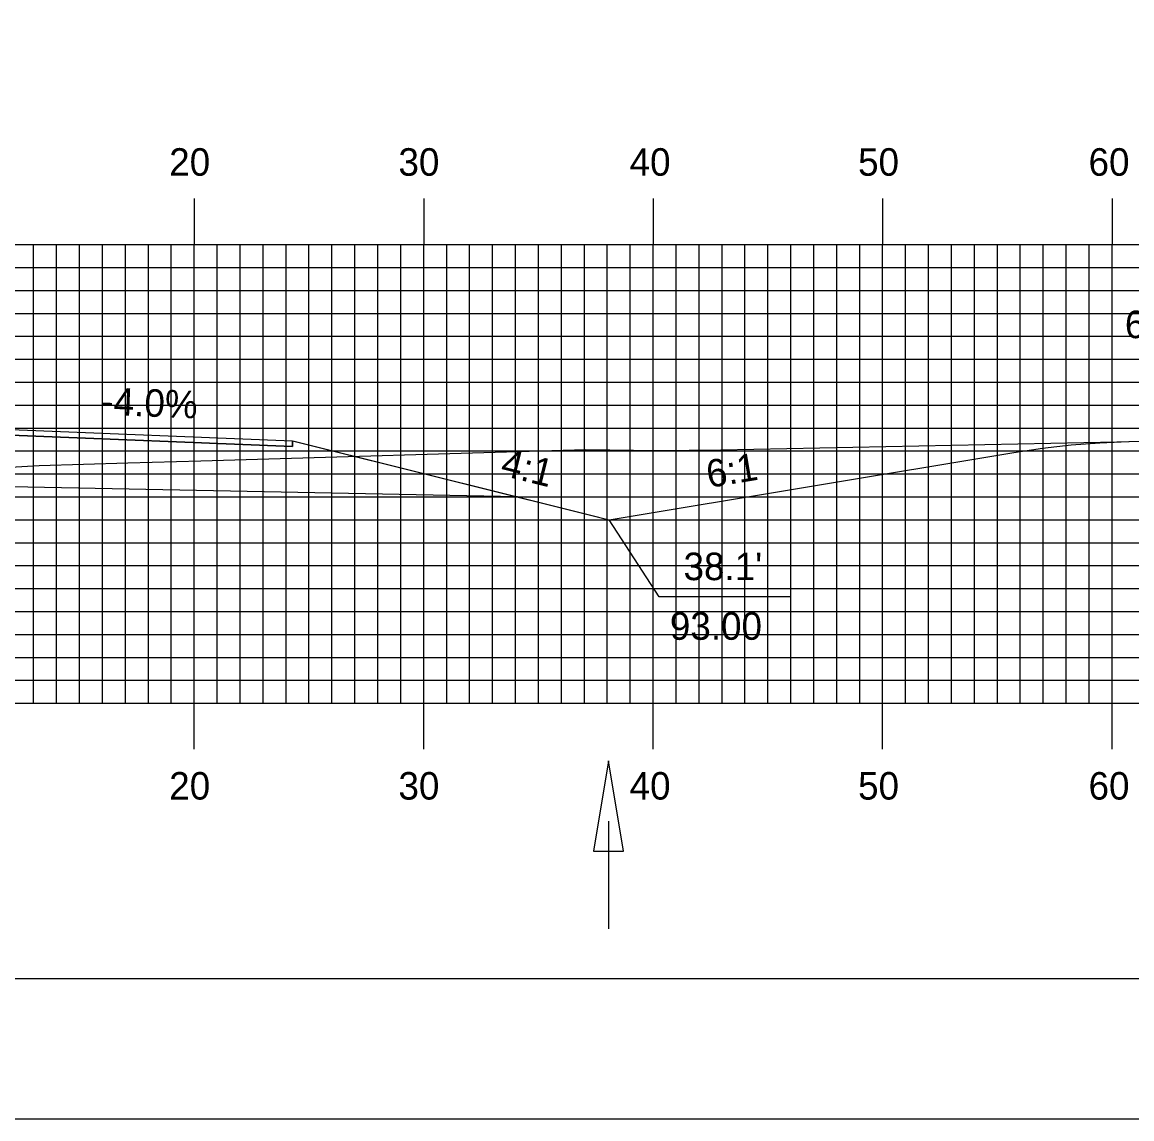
# Model space of a CAD drawing. Extents: x 1775564 to 1775907, y 442591 to 442811.
# Drawn here: x 1775742.21 to 1775790.57, y 442590.55 to 442638.36 of the extents above; entities that cross this region are included whole.
import ezdxf

# ---------------------------------------------------------------- set-up
doc = ezdxf.new("R2010")
doc.units = 0
for name, color, linetype in [('ANNOTATION', 7, 'Continuous'), ('BORDER', 7, 'Continuous'), ('D_Drainage_Ditch_Line', 7, 'Continuous'), ('D_Roadway_Centerline', 7, 'Continuous'), ('D_Roadway_Edge_Shoulder', 7, 'Continuous'), ('D_Roadway_SlopeLines', 7, 'Continuous'), ('D_Roadway_SubGrade', 7, 'Continuous'), ('D_Text_Standard', 7, 'Continuous'), ('H_V ANNOTATION', 7, 'Continuous'), ('MAJOR', 7, 'Continuous'), ('MINOR', 7, 'Continuous'), ('PLOT BOUNDARY', 7, 'Continuous'), ('S_Roadway_Centerline', 7, 'Continuous')]:
    doc.layers.add(name, color=color, linetype=linetype)

msp = doc.modelspace()

# ---------------------------------------------------------------- linework, layer by layer
at = {"layer": 'ANNOTATION'}
msp.add_lwpolyline([(1775775.668, 442613.306), (1775769.977, 442613.306), (1775767.799, 442616.662)], dxfattribs=at)
at = {"layer": 'BORDER'}
msp.add_lwpolyline([(1775580.111, 442596.665), (1775900.111, 442596.665), (1775900.111, 442806.665), (1775580.111, 442806.665)], close=True, dxfattribs=at)
at = {"layer": 'D_Drainage_Ditch_Line'}
msp.add_line((1775767.763, 442603.524), (1775767.763, 442598.825), dxfattribs=at)
msp.add_lwpolyline([(1775767.107, 442602.211), (1775768.419, 442602.211), (1775767.763, 442606.148)], close=True, dxfattribs=at)
at = {"layer": 'D_Roadway_Centerline'}
msp.add_lwpolyline([(1775741.711, 442620.604), (1775753.997, 442620.112), (1775754.058, 442620.097), (1775763.799, 442617.662), (1775766.937, 442616.878), (1775767.799, 442616.662), (1775785.431, 442619.6), (1775786.68, 442619.786), (1775787.929, 442619.927), (1775787.929, 442619.927), (1775789.181, 442620.022), (1775790.429, 442620.072)], dxfattribs=at)
at = {"layer": 'D_Roadway_Edge_Shoulder'}
msp.add_lwpolyline([(1775741.711, 442620.604), (1775753.997, 442620.112), (1775753.997, 442619.862), (1775741.711, 442620.354)], close=True, dxfattribs=at)
at = {"layer": 'D_Roadway_SlopeLines'}
for points in [[(1775753.997, 442620.112), (1775767.799, 442616.662)], [(1775767.799, 442616.662), (1775785.43, 442619.6), (1775786.68, 442619.786), (1775787.929, 442619.927), (1775789.18, 442620.022), (1775790.429, 442620.072)]]:
    msp.add_lwpolyline(points, dxfattribs=at)
at = {"layer": 'D_Roadway_SubGrade'}
msp.add_lwpolyline([(1775717.712, 442618.104), (1775699.537, 442617.74), (1775709.711, 442620.284), (1775709.711, 442620.034), (1775717.712, 442620.354), (1775729.712, 442620.594), (1775741.711, 442620.354), (1775753.997, 442619.862), (1775753.997, 442620.112), (1775763.798, 442617.662), (1775741.711, 442618.104), (1775729.712, 442618.344)], close=True, dxfattribs=at)
at = {"layer": 'MAJOR'}
for p, q in [((1775749.711, 442630.669), (1775749.711, 442628.665)), ((1775759.711, 442630.669), (1775759.711, 442628.665)), ((1775769.711, 442630.669), (1775769.711, 442628.665)), ((1775779.711, 442630.669), (1775779.711, 442628.665)), ((1775789.711, 442630.669), (1775789.711, 442628.665)), ((1775589.711, 442628.665), (1775869.711, 442628.665)), ((1775589.711, 442628.665), (1775869.711, 442628.665)), ((1775749.711, 442608.665), (1775749.711, 442628.665)), ((1775759.711, 442608.665), (1775759.711, 442628.665)), ((1775769.711, 442608.665), (1775769.711, 442628.665)), ((1775779.711, 442608.665), (1775779.711, 442628.665)), ((1775789.711, 442608.665), (1775789.711, 442628.665)), ((1775589.711, 442623.665), (1775869.711, 442623.665)), ((1775589.711, 442618.665), (1775869.711, 442618.665)), ((1775589.711, 442613.665), (1775869.711, 442613.665)), ((1775589.711, 442608.665), (1775869.711, 442608.665)), ((1775589.711, 442608.665), (1775869.711, 442608.665)), ((1775749.711, 442606.661), (1775749.711, 442608.665)), ((1775759.711, 442606.661), (1775759.711, 442608.665)), ((1775769.711, 442606.661), (1775769.711, 442608.665)), ((1775779.711, 442606.661), (1775779.711, 442608.665)), ((1775789.711, 442606.661), (1775789.711, 442608.665))]:
    msp.add_line(p, q, dxfattribs=at)
at = {"layer": 'MINOR'}
for p, q in [((1775742.711, 442608.665), (1775742.711, 442628.665)), ((1775743.711, 442608.665), (1775743.711, 442628.665)), ((1775744.711, 442608.665), (1775744.711, 442628.665)), ((1775745.711, 442608.665), (1775745.711, 442628.665)), ((1775746.711, 442608.665), (1775746.711, 442628.665)), ((1775747.711, 442608.665), (1775747.711, 442628.665)), ((1775748.711, 442608.665), (1775748.711, 442628.665)), ((1775750.711, 442608.665), (1775750.711, 442628.665)), ((1775751.711, 442608.665), (1775751.711, 442628.665)), ((1775752.711, 442608.665), (1775752.711, 442628.665)), ((1775753.711, 442608.665), (1775753.711, 442628.665)), ((1775754.711, 442608.665), (1775754.711, 442628.665)), ((1775755.711, 442608.665), (1775755.711, 442628.665)), ((1775756.711, 442608.665), (1775756.711, 442628.665)), ((1775757.711, 442608.665), (1775757.711, 442628.665)), ((1775758.711, 442608.665), (1775758.711, 442628.665)), ((1775760.711, 442608.665), (1775760.711, 442628.665)), ((1775761.711, 442608.665), (1775761.711, 442628.665)), ((1775762.711, 442608.665), (1775762.711, 442628.665)), ((1775763.711, 442608.665), (1775763.711, 442628.665)), ((1775764.711, 442608.665), (1775764.711, 442628.665)), ((1775765.711, 442608.665), (1775765.711, 442628.665)), ((1775766.711, 442608.665), (1775766.711, 442628.665)), ((1775767.711, 442608.665), (1775767.711, 442628.665)), ((1775768.711, 442608.665), (1775768.711, 442628.665)), ((1775770.711, 442608.665), (1775770.711, 442628.665)), ((1775771.711, 442608.665), (1775771.711, 442628.665)), ((1775772.711, 442608.665), (1775772.711, 442628.665)), ((1775773.711, 442608.665), (1775773.711, 442628.665)), ((1775774.711, 442608.665), (1775774.711, 442628.665)), ((1775775.711, 442608.665), (1775775.711, 442628.665)), ((1775776.711, 442608.665), (1775776.711, 442628.665)), ((1775777.711, 442608.665), (1775777.711, 442628.665)), ((1775778.711, 442608.665), (1775778.711, 442628.665)), ((1775780.711, 442608.665), (1775780.711, 442628.665)), ((1775781.711, 442608.665), (1775781.711, 442628.665)), ((1775782.711, 442608.665), (1775782.711, 442628.665)), ((1775783.711, 442608.665), (1775783.711, 442628.665)), ((1775784.711, 442608.665), (1775784.711, 442628.665)), ((1775785.711, 442608.665), (1775785.711, 442628.665)), ((1775786.711, 442608.665), (1775786.711, 442628.665)), ((1775787.711, 442608.665), (1775787.711, 442628.665)), ((1775788.711, 442608.665), (1775788.711, 442628.665)), ((1775589.711, 442627.665), (1775869.711, 442627.665)), ((1775589.711, 442626.665), (1775869.711, 442626.665)), ((1775589.711, 442625.665), (1775869.711, 442625.665)), ((1775589.711, 442624.665), (1775869.711, 442624.665)), ((1775589.711, 442622.665), (1775869.711, 442622.665)), ((1775589.711, 442621.665), (1775869.711, 442621.665)), ((1775589.711, 442620.665), (1775869.711, 442620.665)), ((1775589.711, 442619.665), (1775869.711, 442619.665)), ((1775589.711, 442617.665), (1775869.711, 442617.665)), ((1775589.711, 442616.665), (1775869.711, 442616.665)), ((1775589.711, 442615.665), (1775869.711, 442615.665)), ((1775589.711, 442614.665), (1775869.711, 442614.665)), ((1775589.711, 442612.665), (1775869.711, 442612.665)), ((1775589.711, 442611.665), (1775869.711, 442611.665)), ((1775589.711, 442610.665), (1775869.711, 442610.665)), ((1775589.711, 442609.665), (1775869.711, 442609.665))]:
    msp.add_line(p, q, dxfattribs=at)
at = {"layer": 'PLOT BOUNDARY'}
msp.add_lwpolyline([(1775563.925, 442590.547), (1775903.925, 442590.547), (1775903.925, 442810.547), (1775563.925, 442810.547)], close=True, dxfattribs=at)
at = {"layer": 'S_Roadway_Centerline'}
msp.add_lwpolyline([(1775671.367, 442617.314), (1775677.368, 442617.226), (1775681.932, 442617.369), (1775694.75, 442617.701), (1775704.446, 442617.76), (1775718.287, 442617.975), (1775727.836, 442618.408), (1775734.374, 442618.543), (1775742.951, 442619.027), (1775746.809, 442619.145), (1775750.001, 442619.229), (1775766.783, 442619.727), (1775769.905, 442619.679), (1775772.654, 442619.714), (1775789.917, 442620.057), (1775792.569, 442620.138)], dxfattribs=at)

# ---------------------------------------------------------------- texts
at = {"layer": 'ANNOTATION'}
for s, rotation, p in [('-4.0%', 357.7069, (1775745.646, 442621.248)), ('4:1', 345.9653, (1775763.006, 442618.619)), ('6:1', 9.4604, (1775772.135, 442618.051))]:
    msp.add_text(s, height=1.2, rotation=rotation, dxfattribs=at).set_placement(p)
for s, p in [("38.1'", (1775771.033, 442614.032)), ('93.00', (1775770.438, 442611.432))]:
    msp.add_text(s, height=1.2, dxfattribs=at).set_placement(p)
at = {"layer": 'D_Text_Standard'}
msp.add_text("60.8'", height=1.2, dxfattribs=at).set_placement((1775790.269, 442624.583))
at = {"layer": 'H_V ANNOTATION'}
for s, p in [('20', (1775748.619, 442631.665)), ('30', (1775758.609, 442631.665)), ('40', (1775768.684, 442631.665)), ('50', (1775778.641, 442631.665)), ('60', (1775788.684, 442631.665)), ('20', (1775748.619, 442604.465)), ('30', (1775758.609, 442604.465)), ('40', (1775768.684, 442604.465)), ('50', (1775778.641, 442604.465)), ('60', (1775788.684, 442604.465))]:
    msp.add_text(s, height=1.2, dxfattribs=at).set_placement(p)

doc.saveas('drawing.dxf')
